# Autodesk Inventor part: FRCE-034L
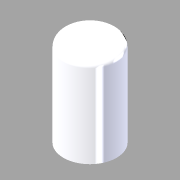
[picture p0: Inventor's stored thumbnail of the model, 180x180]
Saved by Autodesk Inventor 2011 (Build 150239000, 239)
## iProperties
Created: 2011-03
Part Number: FRCE-034L
Document SubType Name: Modeling
Designer: tananaev
Density: 1 g/cm^3
Mass: 977.758 g
Surface Area: 618.216 cm^2
Volume: 977.758 cm^3
Author: tananaev
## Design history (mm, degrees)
sketch "Эскиз1"
  geometry: C1 r 66 at (0, 0); 1 further point
  constraints: 1 centre point, 1 coincident
  dimensions: "d0" = 132 diameter of C1
extrude "Выдавливание1" new body sketch "Эскиз1" distance "d1" = 226; taper "d2" = 0 deg
fillet "Сопряжение1" dims "d3" = 20
sketch "Эскиз2"
  geometry: C1 r 66 at (0, 0) reference; C2 r 36 at (0, 0); C3 r 31.5 at (0, 0); C4 r 66 at (0, 0) reference; C5 r 45 at (0, 0)
  constraints: 3 centre point, 3 coincident
  dimensions: "d4" = 72 diameter of C2; "d5" = 63 diameter of C3; "d8" = 90 diameter of C5
extrude "Выдавливание3" cut sketch "Эскиз2" distance "d9" = 6; taper "d10" = 0 deg
hole "Отверстие1" diameter "d13" = 38.952; stored, may be unused: countersink angle "d17" = 90 deg, drill point angle "d19" = 118 deg; dims "d11" = 10, "d12" = 10, "d14" = 6, "d15" = 4, "d16" = 2, "d18" = 20
node "Твердое тело1"
